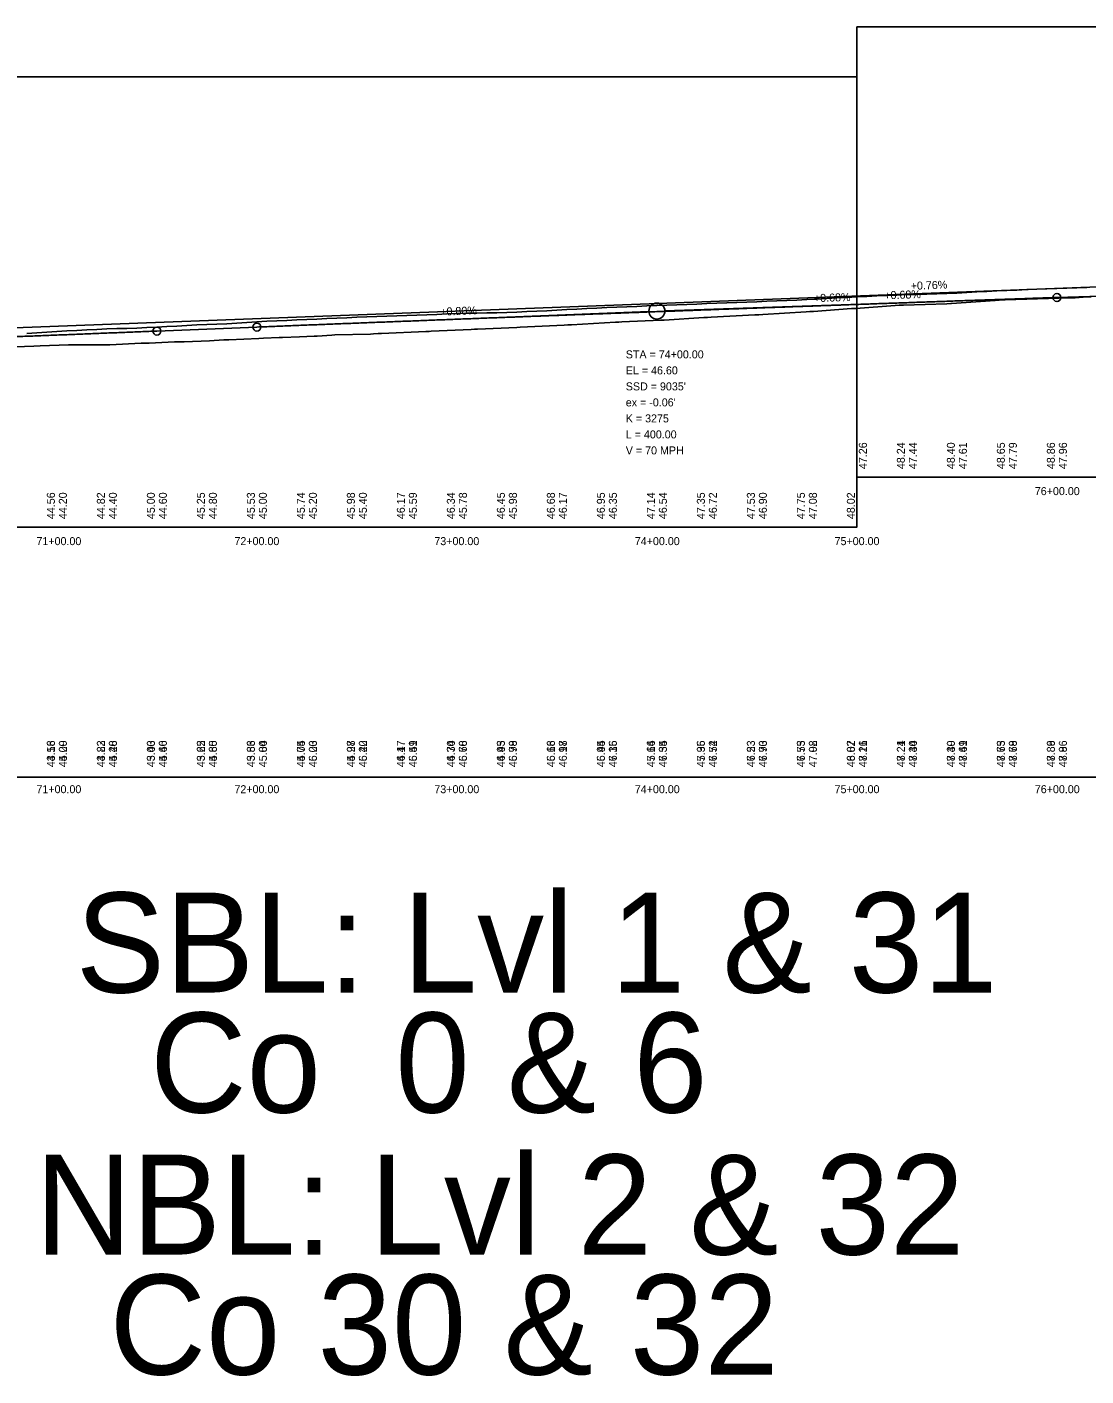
# Model space of a CAD drawing. Extents: x 3880794 to 3915434, y 287517 to 300173.
# Drawn here: x 3887623 to 3888153, y 297425 to 298099 of the extents above; entities that cross this region are included whole.
import ezdxf

# ---------------------------------------------------------------- set-up
doc = ezdxf.new("R2010")
doc.units = 0
for name, color, linetype in [('Level 1', 7, 'Continuous'), ('Level 2', 7, 'Continuous'), ('Level 30', 7, 'Continuous'), ('Level 31', 7, 'Continuous'), ('Level 32', 7, 'Continuous'), ('Level 62', 7, 'Continuous'), ('Level 63', 7, 'Continuous')]:
    doc.layers.add(name, color=color, linetype=linetype)

msp = doc.modelspace()

# ---------------------------------------------------------------- linework, layer by layer
at = {"layer": 'Level 1'}
for p, q in [((3888138.3, 297963.97), (3887942.29, 297957.33)), ((3888138.3, 297963.97), (3888160.24, 297964.71)), ((3887738.3, 297949.19), (3887934.3, 297957.03)), ((3887688.3, 297947.19), (3887738.3, 297949.19)), ((3887688.3, 297947.19), (3887492.29, 297939.35))]:
    msp.add_line(p, q, dxfattribs=at)
msp.add_lwpolyline([(3887613.02, 297939.16), (3887626.71, 297939.64), (3887629.88, 297939.82), (3887644.18, 297940.28), (3887647.21, 297940.28), (3887661.54, 297940.33), (3887664.74, 297940.34), (3887680.5, 297941.09), (3887684.5, 297941.15), (3887697.12, 297941.76), (3887702.04, 297941.85), (3887714.66, 297942.37), (3887721.72, 297942.78), (3887724.3, 297942.75), (3887739.21, 297943.52), (3887741.66, 297943.63), (3887749.51, 297943.92), (3887750.4, 297943.95), (3887751.06, 297944), (3887759.69, 297944.29), (3887766.97, 297944.59), (3887768.46, 297944.71), (3887775.84, 297945.15), (3887777.36, 297945.26), (3887795.08, 297945.68), (3887796.6, 297945.78), (3887798.91, 297945.9), (3887800.57, 297945.99), (3887822.71, 297946.94), (3887823.96, 297947.01), (3887824.43, 297947.03), (3887825.53, 297947.09), (3887845.44, 297948.02), (3887847.04, 297948.08), (3887848.56, 297948.13), (3887868.23, 297949.05), (3887869.96, 297949.11), (3887892.01, 297950.19), (3887893.75, 297950.31), (3887895.56, 297950.38), (3887917.56, 297951.61), (3887919.28, 297951.67), (3887920.73, 297951.76), (3887940.36, 297952.56), (3887941.99, 297952.66), (3887961.81, 297953.91), (3887963.65, 297954.03), (3887965.44, 297954.2), (3887987.23, 297955.26), (3887988.95, 297955.36), (3887989.34, 297955.38), (3887991.26, 297955.49), (3888012.92, 297956.84), (3888014.73, 297956.95), (3888016.6, 297957.05), (3888035.69, 297958.48), (3888037.77, 297958.52), (3888057.52, 297960.03), (3888059.52, 297960.07), (3888061.55, 297960.18), (3888083.26, 297960.81), (3888085.22, 297960.93), (3888085.56, 297960.94), (3888107.44, 297962.47), (3888109.51, 297962.63), (3888110.82, 297962.73), (3888112.39, 297962.81), (3888134.15, 297963.5), (3888135.21, 297963.58), (3888135.68, 297963.64), (3888136.51, 297963.64), (3888137.15, 297963.69), (3888139.34, 297963.56), (3888147.45, 297963.79), (3888151.4, 297964.06), (3888155.49, 297964.25)], dxfattribs=at)
msp.add_circle((3887938.3, 297957.19), 4, dxfattribs=at)
for points in [[(3887738.3, 297949.19), (3887746.3, 297949.51), (3887754.3, 297949.83), (3887762.3, 297950.15), (3887770.3, 297950.46), (3887778.3, 297950.78), (3887786.3, 297951.09), (3887794.3, 297951.41), (3887802.3, 297951.72), (3887810.3, 297952.03), (3887818.3, 297952.34), (3887826.3, 297952.65), (3887834.3, 297952.96), (3887842.3, 297953.27), (3887850.3, 297953.58), (3887858.3, 297953.88), (3887866.3, 297954.18), (3887874.3, 297954.49), (3887882.3, 297954.79), (3887890.3, 297955.09), (3887898.3, 297955.4), (3887906.3, 297955.7), (3887914.3, 297955.99), (3887922.3, 297956.29), (3887930.3, 297956.59), (3887938.3, 297956.89), (3887946.3, 297957.18), (3887954.3, 297957.47), (3887962.3, 297957.77), (3887970.3, 297958.06), (3887978.3, 297958.35), (3887986.3, 297958.64), (3887994.3, 297958.93), (3888002.3, 297959.22), (3888010.3, 297959.51), (3888018.3, 297959.79), (3888026.3, 297960.08), (3888034.3, 297960.36), (3888042.3, 297960.65), (3888050.3, 297960.93), (3888058.3, 297961.21), (3888066.3, 297961.49), (3888074.3, 297961.77), (3888082.3, 297962.05), (3888090.3, 297962.33), (3888098.3, 297962.6), (3888106.3, 297962.88), (3888114.3, 297963.15), (3888122.3, 297963.42), (3888130.3, 297963.7), (3888138.3, 297963.97)], [(3887288.3, 297931.38), (3887296.3, 297931.69), (3887304.3, 297932), (3887312.3, 297932.31), (3887320.3, 297932.63), (3887328.3, 297932.94), (3887336.3, 297933.25), (3887344.3, 297933.57), (3887352.3, 297933.88), (3887360.3, 297934.2), (3887368.3, 297934.51), (3887376.3, 297934.82), (3887384.3, 297935.14), (3887392.3, 297935.45), (3887400.3, 297935.77), (3887408.3, 297936.08), (3887416.3, 297936.4), (3887424.3, 297936.71), (3887432.3, 297937.03), (3887440.3, 297937.34), (3887448.3, 297937.66), (3887456.3, 297937.97), (3887464.3, 297938.29), (3887472.3, 297938.6), (3887480.3, 297938.92), (3887488.3, 297939.24), (3887496.3, 297939.55), (3887504.3, 297939.87), (3887512.3, 297940.19), (3887520.3, 297940.5), (3887528.3, 297940.82), (3887536.3, 297941.14), (3887544.3, 297941.45), (3887552.3, 297941.77), (3887560.3, 297942.09), (3887568.3, 297942.41), (3887576.3, 297942.73), (3887584.3, 297943.04), (3887592.3, 297943.36), (3887600.3, 297943.68), (3887608.3, 297944), (3887616.3, 297944.32), (3887624.3, 297944.64), (3887632.3, 297944.95), (3887640.3, 297945.27), (3887648.3, 297945.59), (3887656.3, 297945.91), (3887664.3, 297946.23), (3887672.3, 297946.55), (3887680.3, 297946.87), (3887688.3, 297947.19)]]:
    msp.add_spline(points, degree=3, dxfattribs=at)
at = {"layer": 'Level 2'}
msp.add_line((3887438.3, 297942.07), (3888173.3, 297969.84), dxfattribs=at)
for points in [[(3888038.3, 297964.29), (3888043.3, 297964.52), (3888048.3, 297964.75), (3888053.3, 297964.98), (3888058.3, 297965.21), (3888063.3, 297965.41), (3888068.3, 297965.54), (3888073.3, 297965.67), (3888078.3, 297965.81), (3888083.3, 297965.95), (3888088.3, 297966.2), (3888093.3, 297966.46), (3888098.3, 297966.72), (3888103.3, 297966.98), (3888108.3, 297967.22), (3888113.3, 297967.44), (3888118.3, 297967.66), (3888123.3, 297967.89), (3888128.3, 297968.14), (3888133.3, 297968.34), (3888138.3, 297968.49), (3888143.3, 297968.64), (3888148.3, 297968.79), (3888153.3, 297968.97)], [(3887623.3, 297946), (3887628.3, 297946.33), (3887633.3, 297946.66), (3887638.3, 297946.98), (3887643.3, 297947.26), (3887648.3, 297947.52), (3887653.3, 297947.78), (3887658.3, 297948.04), (3887663.3, 297948.29), (3887668.3, 297948.42), (3887673.3, 297948.55), (3887678.3, 297948.68), (3887683.3, 297948.9), (3887688.3, 297949.17), (3887693.3, 297949.45), (3887698.3, 297949.72), (3887703.3, 297950.03), (3887708.3, 297950.25), (3887713.3, 297950.46), (3887718.3, 297950.68), (3887723.3, 297950.89), (3887728.3, 297951.19), (3887733.3, 297951.51), (3887738.3, 297951.83), (3887743.3, 297952.14), (3887748.3, 297952.36), (3887753.3, 297952.55), (3887758.3, 297952.73), (3887763.3, 297952.91), (3887768.3, 297953.13), (3887773.3, 297953.4), (3887778.3, 297953.63), (3887783.3, 297953.87), (3887788.3, 297954.1), (3887793.3, 297954.28), (3887798.3, 297954.47), (3887803.3, 297954.65), (3887808.3, 297954.84), (3887813.3, 297955.03), (3887818.3, 297955.17), (3887823.3, 297955.36), (3887828.3, 297955.54), (3887833.3, 297955.73), (3887838.3, 297955.91), (3887843.3, 297956.07), (3887848.3, 297956.17), (3887853.3, 297956.26), (3887858.3, 297956.36), (3887863.3, 297956.46), (3887868.3, 297956.71), (3887873.3, 297956.93), (3887878.3, 297957.16), (3887883.3, 297957.38), (3887888.3, 297957.61), (3887893.3, 297957.92), (3887898.3, 297958.19), (3887903.3, 297958.46), (3887908.3, 297958.72), (3887913.3, 297958.94), (3887918.3, 297959.14), (3887923.3, 297959.34), (3887928.3, 297959.54), (3887933.3, 297959.74), (3887938.3, 297959.91), (3887943.3, 297960.12), (3887948.3, 297960.32), (3887953.3, 297960.52), (3887958.3, 297960.72), (3887963.3, 297960.94), (3887968.3, 297961.13), (3887973.3, 297961.32), (3887978.3, 297961.49), (3887983.3, 297961.68), (3887988.3, 297961.86), (3887993.3, 297962.08), (3887998.3, 297962.29), (3888003.3, 297962.5), (3888008.3, 297962.7), (3888013.3, 297962.94), (3888018.3, 297963.21), (3888023.3, 297963.49), (3888028.3, 297963.76), (3888033.3, 297964.03), (3888038.3, 297964.29)]]:
    msp.add_lwpolyline(points, dxfattribs=at)
at = {"layer": 'Level 31'}
for centre in [(3888138.3, 297963.97), (3887688.3, 297947.19), (3887738.3, 297949.19)]:
    msp.add_circle(centre, 2, dxfattribs=at)
at = {"layer": 'Level 62'}
for points in [[(3888038.3, 297874.19), (3888738.3, 297874.19), (3888738.3, 298099.19), (3888038.3, 298099.19)], [(3888038.3, 297874.19), (3888738.3, 297874.19), (3888738.3, 298099.19), (3888038.3, 298099.19)], [(3887338.3, 297849.19), (3888038.3, 297849.19), (3888038.3, 298074.19), (3887338.3, 298074.19)], [(3887338.3, 297849.19), (3888038.3, 297849.19), (3888038.3, 298074.19), (3887338.3, 298074.19)]]:
    msp.add_lwpolyline(points, close=True, dxfattribs=at)
at = {"layer": 'Level 63'}
msp.add_line((3881538.3, 297724.19), (3896411.35, 297724.19), dxfattribs=at)

# ---------------------------------------------------------------- texts
at = {"layer": 'Level 1'}
for s, p in [('SBL: Lvl 1 & 31', (3887647.76, 297616.55)), ('  Co  0 & 6', (3887647.76, 297556.55))]:
    msp.add_text(s, height=50, dxfattribs=at).set_placement(p)
at = {"layer": 'Level 2'}
msp.add_text('+0.76%', height=4, rotation=2.16347, dxfattribs=at).set_placement((3888065.3, 297967.76))
for s, p in [('NBL: Lvl 2 & 32', (3887627.47, 297485.58)), ('  Co 30 & 32', (3887627.47, 297425.58))]:
    msp.add_text(s, height=50, dxfattribs=at).set_placement(p)
at = {"layer": 'Level 30'}
for s, p in [('76+00.00', (3888127.27, 297865.19)), ('76+00.00', (3888127.27, 297865.19)), ('71+00.00', (3887628.09, 297840.19)), ('71+00.00', (3887628.09, 297840.19)), ('72+00.00', (3887727.09, 297840.19)), ('72+00.00', (3887727.09, 297840.19)), ('73+00.00', (3887827.05, 297840.19)), ('73+00.00', (3887827.05, 297840.19)), ('74+00.00', (3887927.27, 297840.19)), ('74+00.00', (3887927.27, 297840.19)), ('75+00.00', (3888027.15, 297840.19)), ('75+00.00', (3888027.15, 297840.19)), ('71+00.00', (3887628.09, 297716.19)), ('71+00.00', (3887628.09, 297716.19)), ('72+00.00', (3887727.09, 297716.19)), ('72+00.00', (3887727.09, 297716.19)), ('73+00.00', (3887827.05, 297716.19)), ('73+00.00', (3887827.05, 297716.19)), ('74+00.00', (3887927.27, 297716.19)), ('74+00.00', (3887927.27, 297716.19)), ('75+00.00', (3888027.15, 297716.19)), ('75+00.00', (3888027.15, 297716.19)), ('76+00.00', (3888127.27, 297716.19)), ('76+00.00', (3888127.27, 297716.19))]:
    msp.add_text(s, height=4, dxfattribs=at).set_placement(p)
at = {"layer": 'Level 31'}
for s, rotation, p in [('+0.68%', 1.94123, (3888016.89, 297961.63)), ('+0.68%', 1.94123, (3888052.08, 297963.05)), ('+0.80%', 2.29061, (3887830.08, 297954.86)), ('47.26', 90, (3888043.3, 297878.19)), ('47.44', 90, (3888068.3, 297878.19)), ('47.61', 90, (3888093.3, 297878.19)), ('47.79', 90, (3888118.3, 297878.19)), ('47.96', 90, (3888143.3, 297878.19)), ('44.20', 90, (3887643.3, 297853.19)), ('44.40', 90, (3887668.3, 297853.19)), ('44.60', 90, (3887693.3, 297853.19)), ('44.80', 90, (3887718.3, 297853.19)), ('45.00', 90, (3887743.3, 297853.19)), ('45.20', 90, (3887768.3, 297853.19)), ('45.40', 90, (3887793.3, 297853.19)), ('45.59', 90, (3887818.3, 297853.19)), ('45.78', 90, (3887843.3, 297853.19)), ('45.98', 90, (3887868.3, 297853.19)), ('46.17', 90, (3887893.3, 297853.19)), ('46.35', 90, (3887918.3, 297853.19)), ('46.54', 90, (3887943.3, 297853.19)), ('46.72', 90, (3887968.3, 297853.19)), ('46.90', 90, (3887993.3, 297853.19)), ('47.08', 90, (3888018.3, 297853.19)), ('43.18', 90, (3887637.3, 297729.19)), ('44.20', 90, (3887643.3, 297729.19)), ('43.23', 90, (3887662.3, 297729.19)), ('44.40', 90, (3887668.3, 297729.19)), ('43.43', 90, (3887687.3, 297729.19)), ('44.60', 90, (3887693.3, 297729.19)), ('43.62', 90, (3887712.3, 297729.19)), ('44.80', 90, (3887718.3, 297729.19)), ('43.86', 90, (3887737.3, 297729.19)), ('45.00', 90, (3887743.3, 297729.19)), ('44.05', 90, (3887762.3, 297729.19)), ('45.20', 90, (3887768.3, 297729.19)), ('44.27', 90, (3887787.3, 297729.19)), ('45.40', 90, (3887793.3, 297729.19)), ('44.47', 90, (3887812.3, 297729.19)), ('45.59', 90, (3887818.3, 297729.19)), ('44.70', 90, (3887837.3, 297729.19)), ('45.78', 90, (3887843.3, 297729.19)), ('44.93', 90, (3887862.3, 297729.19)), ('45.98', 90, (3887868.3, 297729.19)), ('45.16', 90, (3887887.3, 297729.19)), ('46.17', 90, (3887893.3, 297729.19)), ('45.44', 90, (3887912.3, 297729.19)), ('46.35', 90, (3887918.3, 297729.19)), ('45.66', 90, (3887937.3, 297729.19)), ('46.54', 90, (3887943.3, 297729.19)), ('45.96', 90, (3887962.3, 297729.19)), ('46.72', 90, (3887968.3, 297729.19)), ('46.23', 90, (3887987.3, 297729.19)), ('46.90', 90, (3887993.3, 297729.19)), ('46.53', 90, (3888012.3, 297729.19)), ('47.08', 90, (3888018.3, 297729.19)), ('46.87', 90, (3888037.3, 297729.19)), ('47.26', 90, (3888043.3, 297729.19)), ('47.21', 90, (3888062.3, 297729.19)), ('47.44', 90, (3888068.3, 297729.19)), ('47.39', 90, (3888087.3, 297729.19)), ('47.61', 90, (3888093.3, 297729.19)), ('47.73', 90, (3888112.3, 297729.19)), ('47.79', 90, (3888118.3, 297729.19)), ('47.89', 90, (3888137.3, 297729.19)), ('47.96', 90, (3888143.3, 297729.19))]:
    msp.add_text(s, height=4, rotation=rotation, dxfattribs=at).set_placement(p)
for s, p in [('STA = 74+00.00', (3887922.76, 297933.54)), ('EL = 46.60', (3887922.76, 297925.54)), ("SSD = 9035'", (3887922.76, 297917.54)), ("ex = -0.06'", (3887922.76, 297909.54)), ('K = 3275', (3887922.76, 297901.54)), ('L = 400.00', (3887922.76, 297893.54)), ('V = 70 MPH', (3887922.76, 297885.54))]:
    msp.add_text(s, height=4, dxfattribs=at).set_placement(p)
at = {"layer": 'Level 32'}
for s, p in [('48.24', (3888062.3, 297878.19)), ('48.40', (3888087.3, 297878.19)), ('48.65', (3888112.3, 297878.19)), ('48.86', (3888137.3, 297878.19)), ('44.56', (3887637.3, 297853.19)), ('44.82', (3887662.3, 297853.19)), ('45.00', (3887687.3, 297853.19)), ('45.25', (3887712.3, 297853.19)), ('45.53', (3887737.3, 297853.19)), ('45.74', (3887762.3, 297853.19)), ('45.98', (3887787.3, 297853.19)), ('46.17', (3887812.3, 297853.19)), ('46.34', (3887837.3, 297853.19)), ('46.45', (3887862.3, 297853.19)), ('46.68', (3887887.3, 297853.19)), ('46.95', (3887912.3, 297853.19)), ('47.14', (3887937.3, 297853.19)), ('47.35', (3887962.3, 297853.19)), ('47.53', (3887987.3, 297853.19)), ('47.75', (3888012.3, 297853.19)), ('48.02', (3888037.3, 297853.19)), ('44.56', (3887637.3, 297729.19)), ('45.09', (3887643.3, 297729.19)), ('44.82', (3887662.3, 297729.19)), ('45.28', (3887668.3, 297729.19)), ('45.00', (3887687.3, 297729.19)), ('45.46', (3887693.3, 297729.19)), ('45.25', (3887712.3, 297729.19)), ('45.65', (3887718.3, 297729.19)), ('45.53', (3887737.3, 297729.19)), ('45.84', (3887743.3, 297729.19)), ('45.74', (3887762.3, 297729.19)), ('46.03', (3887768.3, 297729.19)), ('45.98', (3887787.3, 297729.19)), ('46.22', (3887793.3, 297729.19)), ('46.17', (3887812.3, 297729.19)), ('46.41', (3887818.3, 297729.19)), ('46.34', (3887837.3, 297729.19)), ('46.60', (3887843.3, 297729.19)), ('46.45', (3887862.3, 297729.19)), ('46.79', (3887868.3, 297729.19)), ('46.68', (3887887.3, 297729.19)), ('46.98', (3887893.3, 297729.19)), ('46.95', (3887912.3, 297729.19)), ('47.16', (3887918.3, 297729.19)), ('47.14', (3887937.3, 297729.19)), ('47.35', (3887943.3, 297729.19)), ('47.35', (3887962.3, 297729.19)), ('47.54', (3887968.3, 297729.19)), ('47.53', (3887987.3, 297729.19)), ('47.73', (3887993.3, 297729.19)), ('47.75', (3888012.3, 297729.19)), ('47.92', (3888018.3, 297729.19)), ('48.02', (3888037.3, 297729.19)), ('48.11', (3888043.3, 297729.19)), ('48.24', (3888062.3, 297729.19)), ('48.30', (3888068.3, 297729.19)), ('48.40', (3888087.3, 297729.19)), ('48.49', (3888093.3, 297729.19)), ('48.65', (3888112.3, 297729.19)), ('48.68', (3888118.3, 297729.19)), ('48.86', (3888137.3, 297729.19)), ('48.86', (3888143.3, 297729.19))]:
    msp.add_text(s, height=4, rotation=90, dxfattribs=at).set_placement(p)

doc.saveas('drawing.dxf')
